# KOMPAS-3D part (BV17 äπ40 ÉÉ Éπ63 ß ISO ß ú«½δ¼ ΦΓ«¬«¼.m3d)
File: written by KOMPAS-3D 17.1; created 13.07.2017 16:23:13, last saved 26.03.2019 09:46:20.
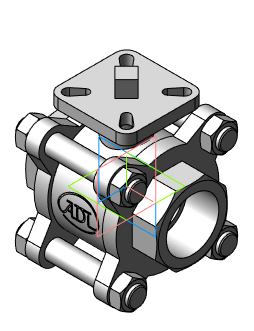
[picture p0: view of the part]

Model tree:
1. Операция без истории:4  (labels: Сталь 20  ГОСТ 1050-88)

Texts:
  DISO1
  DISO2
  BV17 Ду8 1/4" Ру63 с ISO
  BV17 Ду8 СС Ру63 с ISO
  BV17 Ду10 3/8" Ру63 с ISO
  BV17 Ду10 СС Ру63 с ISO
  BV17 Ду15 1/2" Ру63 с ISO
  BV17 Ду15 СС Ру63 с ISO
  BV17 Ду15 ФФ Ру40 с ISO
  BV17 Ду20 3/4" Ру63 с ISO
  BV17 Ду20 СС Ру40 с ISO
  BV17 Ду20 ФФ Ру40 с ISO
  BV17 Ду25 1" Ру63 с ISO
  BV17 Ду25 СС Ру63 с ISO
  BV17 Ду25 ФФ Ру40 с ISO
  BV17 Ду32 1 1/4" Ру63 с ISO
  BV17 Ду32 СС Ру63 с ISO
  BV17 Ду32 ФФ Ру40 с ISO
  BV17 Ду40 1 1/2" Ру63 с ISO
  BV17 Ду40 СС Ру63 с ISO
  BV17 Ду40 ФФ Ру40 с ISO
  BV17 Ду50 2" Ру63 с ISO
  BV17 Ду50 СС Ру63 с ISO
  BV17 Ду50 ФФ Ру40 с ISO
  BV17 Ду65 2 1/2" Ру40 с ISO
  BV17 Ду65 СС Ру40 с ISO
  BV17 Ду65 ФФ Ру40 с ISO
  BV17 Ду80 3" Ру40 с ISO
  BV17 Ду80 СС Ру40 с ISO
  BV17 Ду80 ФФ Ру40 с ISO
  BV17 Ду100 4" Ру40 с ISO
  BV17 Ду100 СС Ру40 с ISO
  BV17 Ду100 ФФ Ру40 с ISO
